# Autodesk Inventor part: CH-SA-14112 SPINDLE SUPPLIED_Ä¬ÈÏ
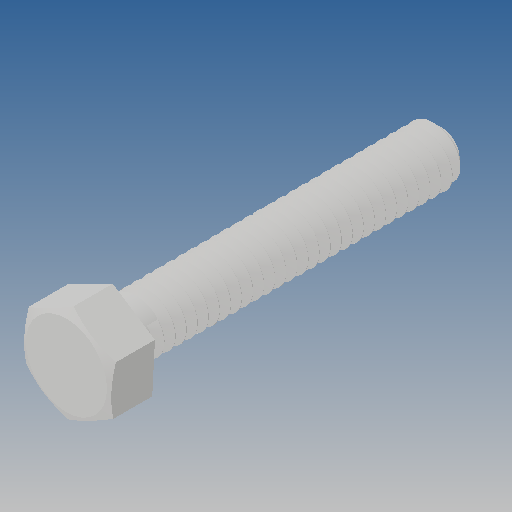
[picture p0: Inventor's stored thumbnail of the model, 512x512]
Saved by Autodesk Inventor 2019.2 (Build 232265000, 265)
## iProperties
Created: 2010-06
Part Number: CH-SA-14112 SPINDLE SUPPLIED_Ä¬ÈÏ
Material: Ogólny
Document SubType Name: Modeling
Designer: CADENGINEERING4
Density: 1 g/cm^3
Appearance: Domyślna
Author: CADENGINEERING4
Revision Number: ÈÎºÎ
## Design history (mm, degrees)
feature "NONE"
node "Bryła1"
